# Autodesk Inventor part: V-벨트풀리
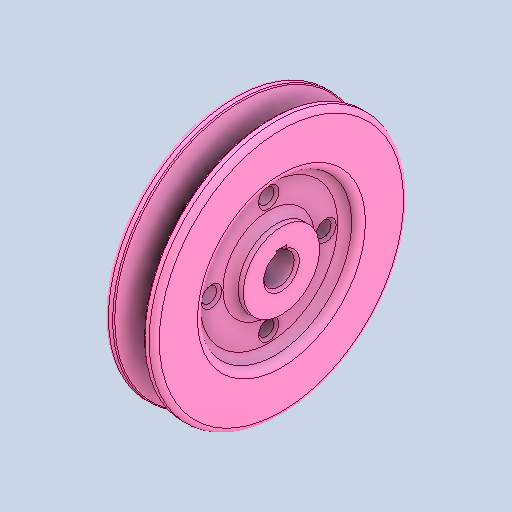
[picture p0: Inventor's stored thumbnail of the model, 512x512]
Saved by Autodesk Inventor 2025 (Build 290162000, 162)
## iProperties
Created: 2024-07
Part Number: V-벨트풀리
Material: 강철, 연강
Document SubType Name: Modeling
Designer: deana
Density: 7.86 g/cm^3
Appearance: 기본값
Author: jhkim
Sending System: Autodesk Inventor 2025
Preprocessor: ST-DEVELOPER v20
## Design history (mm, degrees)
feature "솔리드1"
node "솔리드2"
